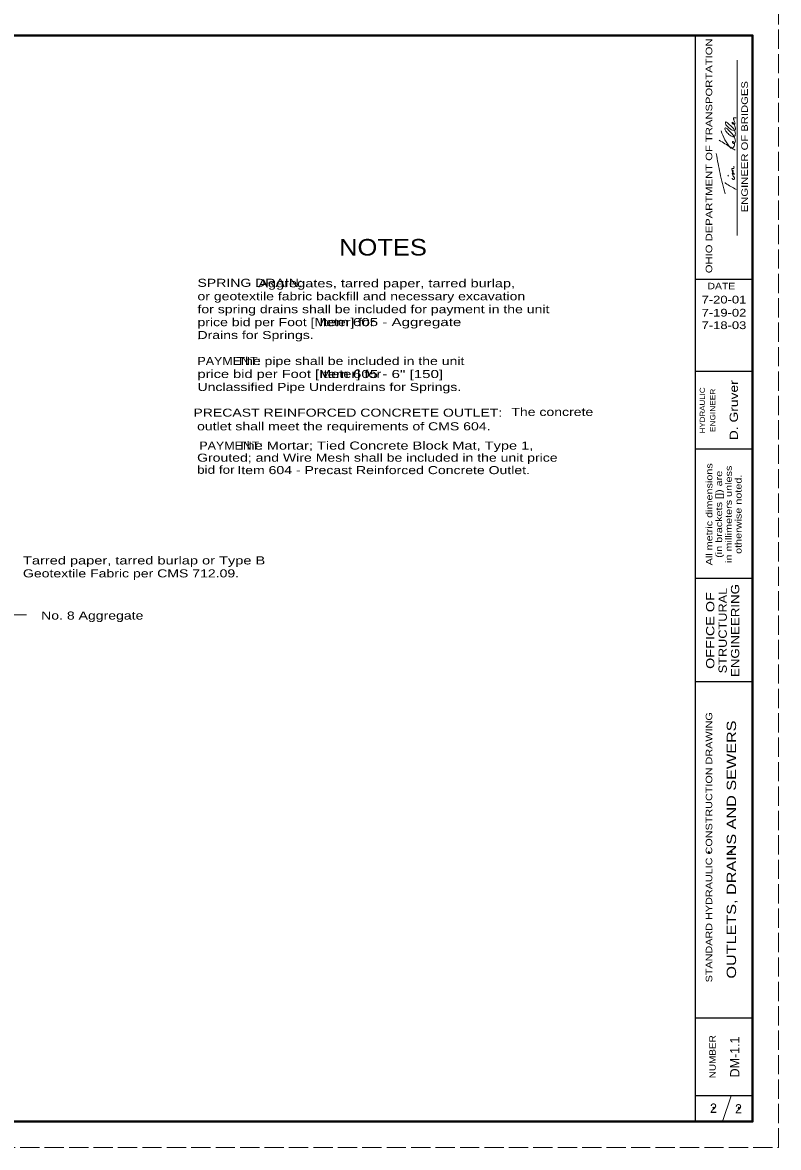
# Model space of a CAD drawing. Extents: x 1083.1 to 1117.1, y 697.4 to 741.4.
# Drawn here: x 1102.52 to 1117.13, y 697.35 to 719.1 of the extents above; entities that cross this region are included whole.
import ezdxf
from ezdxf.enums import TextEntityAlignment as Align

# ---------------------------------------------------------------- set-up
doc = ezdxf.new("R2010")
doc.units = 0
doc.header["$LTSCALE"] = 0.062
doc.header["$PDMODE"] = 32
doc.header["$PDSIZE"] = 0.031
doc.linetypes.add('LONG_DASHED', pattern=[7.5, 6, -1.5])
doc.layers.add('1', color=7, linetype='Continuous', lineweight=13)

msp = doc.modelspace()

# ---------------------------------------------------------------- linework, layer by layer
at = {"layer": '1', "lineweight": 25}
for p, q in [((1085.12642, 718.85408), (1116.62642, 718.85408)), ((1115.52642, 697.85408), (1115.52642, 718.85408)), ((1116.62642, 718.85408), (1116.62642, 697.85408)), ((1116.62642, 714.13825), (1115.52642, 714.13825)), ((1116.62642, 712.35408), (1115.52642, 712.35408)), ((1116.62642, 710.85408), (1115.52642, 710.85408)), ((1116.62642, 708.35408), (1115.52642, 708.35408)), ((1116.62642, 706.35408), (1115.52642, 706.35408)), ((1116.62642, 699.85408), (1115.52642, 699.85408)), ((1116.62642, 698.35408), (1115.52642, 698.35408))]:
    msp.add_line(p, q, dxfattribs=at)
at = {"layer": '1'}
for p, q in [((1116.32517, 714.98508), (1116.32517, 718.37517)), ((1116.15767, 716.136), (1116.1475, 716.15525)), ((1116.04308, 697.85408), (1116.20975, 698.35408))]:
    msp.add_line(p, q, dxfattribs=at)
at = {"layer": '1', "linetype": 'LONG_DASHED'}
msp.add_lwpolyline([(1083.12642, 697.35408), (1117.12642, 697.35408), (1117.12642, 719.35408), (1083.12642, 719.35408)], close=True, dxfattribs=at)
at = {"layer": '1', "lineweight": 25}
msp.add_lwpolyline([(1116.62642, 697.85408), (1085.12642, 697.85408), (1085.12642, 718.85408)], dxfattribs=at)
at = {"layer": '1', "lineweight": 40}
msp.add_lwpolyline([(1085.12642, 718.85408), (1116.62642, 718.85408), (1116.62642, 697.85408), (1085.12642, 697.85408)], close=True, dxfattribs=at)
msp.add_lwpolyline([(1085.12642, 718.85408), (1116.62642, 718.85408), (1116.62642, 697.85408), (1085.12642, 697.85408)], close=True, dxfattribs=at)
at = {"layer": '1'}
msp.add_lwpolyline([(1100.01742, 706.42642), (1102.17033, 707.65183), (1102.60283, 707.65183)], dxfattribs=at)
for points in [[(1116.01825, 717.01108), (1116.20142, 716.68275), (1116.21658, 716.67217), (1116.22675, 716.67217), (1116.25867, 716.69583), (1116.27375, 716.73), (1116.26875, 716.78125), (1116.25183, 716.80308), (1116.23833, 716.80308), (1116.23658, 716.79008), (1116.24675, 716.77492), (1116.26025, 716.7665), (1116.27533, 716.7665), (1116.2905, 716.78808), (1116.29392, 716.80742), (1116.28367, 716.86275), (1116.20142, 716.98317), (1116.15592, 717.02783), (1116.119, 717.06242), (1116.09383, 717.06458), (1116.09558, 717.026), (1116.12075, 716.98725), (1116.188, 716.92492), (1116.23008, 716.8995), (1116.26375, 716.895), (1116.28708, 716.921), (1116.29392, 716.95517), (1116.28883, 716.98092), (1116.25867, 717.05408), (1116.22842, 717.08608), (1116.16783, 717.1395), (1116.13917, 717.16533), (1116.10567, 717.18058), (1116.10225, 717.15258), (1116.11233, 717.12675), (1116.1695, 717.06683), (1116.24017, 717.01958), (1116.29217, 717.02192), (1116.2905, 717.07958), (1116.27867, 717.1225), (1116.26533, 717.14825), (1116.25517, 717.159), (1116.23175, 717.174), (1116.2335, 717.15692), (1116.26875, 717.13542), (1116.28367, 717.14617), (1116.27058, 717.19983), (1116.262, 717.22775), (1116.25867, 717.24042), (1116.25867, 717.25325), (1116.25867, 717.26192), (1116.28367, 717.25975), (1116.30908, 717.25975)], [(1115.97942, 716.82883), (1116.20317, 716.69133), (1116.28883, 716.63567)], [(1116.09567, 715.79183), (1115.997, 716.18708), (1115.92575, 716.56942)], [(1116.22675, 716.09075), (1116.235, 716.08008), (1116.27217, 716.06717), (1116.27692, 716.09958), (1116.25183, 716.136), (1116.23658, 716.17225), (1116.23658, 716.1915), (1116.25183, 716.18525), (1116.262, 716.17442), (1116.27217, 716.17008), (1116.2485, 716.20225), (1116.23658, 716.21725), (1116.2335, 716.23458), (1116.25692, 716.228), (1116.2485, 716.23667), (1116.22333, 716.2645), (1116.2335, 716.27967), (1116.25025, 716.28167), (1116.25867, 716.27967), (1116.26875, 716.301), (1116.262, 716.32892)], [(1116.31083, 715.87625), (1116.10567, 715.99625), (1116.09008, 716.00667)]]:
    msp.add_spline(points, degree=3, dxfattribs=at)
for p in [(1115.78383, 703.06008), (1116.21667, 703.06742), (1115.8745, 698.11783), (1116.36292, 698.11683)]:
    msp.add_point(p, dxfattribs=at)

# ---------------------------------------------------------------- texts
for s, height, width, p in [('OHIO DEPARTMENT OF TRANSPORTATION', 0.125, 1.3, (1115.84633, 716.52633)), ('ENGINEER OF BRIDGES', 0.125, 1.3, (1116.53467, 716.70312)), ('D. Gruver', 0.16, 1.25, (1116.34283, 711.60825)), ('HYDRAULIC', 0.1, 1.15, (1115.7055, 711.60517)), ('ENGINEER', 0.1, 1.2, (1115.90642, 711.60521)), ('All metric dimensions', 0.125, 1.25, (1115.85025, 709.59617)), ('(in brackets []) are', 0.125, 1.25, (1116.03775, 709.59617)), ('in millimeters unless', 0.125, 1.25, (1116.22525, 709.59621)), ('otherwise noted.', 0.125, 1.25, (1116.41275, 709.59617)), ('ENGINEERING', 0.16, 1.2, (1116.36817, 707.34862)), ('OFFICE OF', 0.16, 1.3, (1115.88817, 707.34854)), ('STRUCTURAL', 0.16, 1.15, (1116.12817, 707.34854)), ('STANDARD HYDRAULIC CONSTRUCTION DRAWING', 0.125, 1.25, (1115.84633, 703.15812)), ('OUTLETS, DRAINS AND SEWERS', 0.18, 1.3, (1116.30683, 703.11421)), ('NUMBER', 0.125, 1.15, (1115.91342, 699.10817))]:
    msp.add_text(s, height=height, rotation=90, dxfattribs=dict(at, width=width)).set_placement(p, align=Align.CENTER)
for s, height, width, p in [('NOTES', 0.32, 1.15, (1109.48612, 714.599)), ('DATE', 0.125, 1.2, (1116.02312, 713.94683)), ('7-20-01', 0.15, 1.25, (1116.07346, 713.67133)), ('7-19-02', 0.15, 1.25, (1116.07346, 713.41825)), ('7-18-03', 0.15, 1.25, (1116.07342, 713.17633)), ('PRECAST REINFORCED CONCRETE OUTLET:', 0.156, 1.3, (1108.80687, 711.48308)), ('No. 8 Aggregate', 0.156, 1.3, (1103.86983, 707.5605))]:
    msp.add_text(s, height=height, dxfattribs=dict(at, width=width)).set_placement(p, align=Align.CENTER)
for s, width, p in [('SPRING DRAIN:', 1.3, (1105.9025, 713.99333)), ('               Aggregates, tarred paper, tarred burlap, ', 1.35, (1105.9025, 713.98417)), ('or geotextile fabric backfill and necessary excavation ', 1.3, (1105.9025, 713.73375)), ('for spring drains shall be included for payment in the unit ', 1.3, (1105.9025, 713.48333)), ('price bid per Foot [Meter] for', 1.3, (1105.9025, 713.23292)), ('                             Item 605 - Aggregate ', 1.4, (1105.90225, 713.2345)), ('Drains for Springs.', 1.3, (1105.90225, 712.98408)), ('PAYMENT:', 1.15, (1105.9025, 712.48292)), ('          The pipe shall be included in the unit', 1.3, (1105.9025, 712.48167)), ('price bid per Foot [Meter] for ', 1.35, (1105.9025, 712.23125)), ('                             Item 605 - 6" [150] ', 1.4, (1105.9025, 712.22992)), ('Unclassified Pipe Underdrains for Springs.', 1.3, (1105.9025, 711.9795)), ('The concrete', 1.3, (1111.96558, 711.49708)), ('outlet shall meet the requirements of CMS 604.', 1.3, (1105.89508, 711.21967)), ('          The Mortar; Tied Concrete Block Mat, Type 1, ', 1.35, (1105.89508, 710.84692)), ('PAYMENT:', 1.15, (1105.93925, 710.84667)), ('Grouted; and Wire Mesh shall be included in the unit price ', 1.3, (1105.89508, 710.61292)), ('bid for', 1.25, (1105.89508, 710.37892)), ('    Item 604 - Precast Reinforced Concrete Outlet.', 1.3, (1106.37242, 710.37242)), ('Tarred paper, tarred burlap or Type B', 1.35, (1102.5315, 708.62633)), ('Geotextile Fabric per CMS 712.09.', 1.3, (1102.5315, 708.37592))]:
    msp.add_text(s, height=0.156, dxfattribs=dict(at, width=width)).set_placement(p)
msp.add_text('.', height=0.156, dxfattribs=at).set_placement((1105.9025, 712.98117))
msp.add_text('DM-1.1', height=0.18, rotation=90, dxfattribs=at).set_placement((1116.3725, 699.10442), align=Align.CENTER)
for p in [(1115.87088, 698.02417), (1116.35371, 698.01158)]:
    msp.add_text('2', height=0.18, dxfattribs=at).set_placement(p, align=Align.CENTER)

doc.saveas('drawing.dxf')
